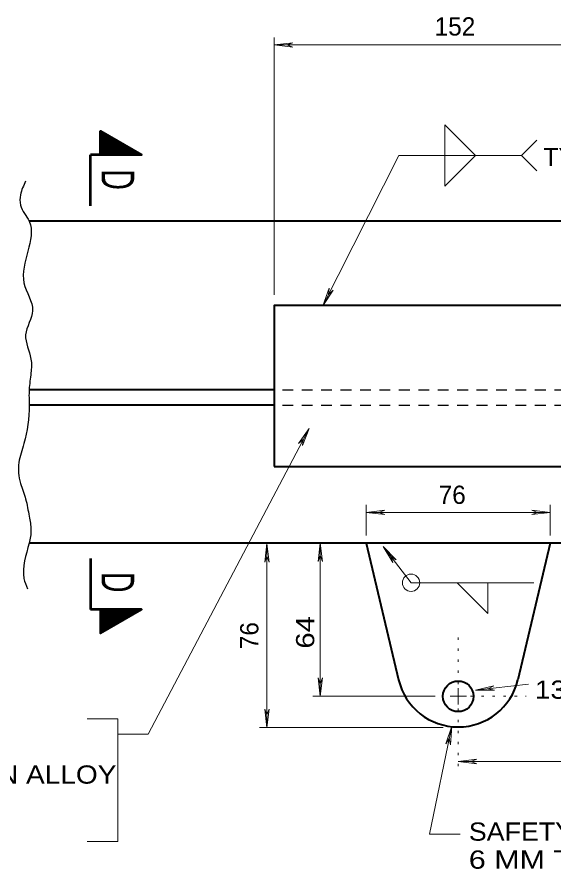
# Model space of a CAD drawing. Extents: x 312583 to 312854, y 144419 to 144597.
# Drawn here: x 312779.22 to 312801.61, y 144485.39 to 144520.9 of the extents above; entities that cross this region are included whole.
import ezdxf
from ezdxf.enums import TextEntityAlignment as Align

# ---------------------------------------------------------------- set-up
doc = ezdxf.new("R2010")
doc.units = 0
doc.header["$LTSCALE"] = 0.3
doc.linetypes.add('DOTTED', pattern=[1.5, 0.3, -1.2])
doc.linetypes.add('SHORT_DASHED', pattern=[2.7, 1.5, -1.2])
doc.layers.add('1', color=7, linetype='Continuous', lineweight=40)

msp = doc.modelspace()

# ---------------------------------------------------------------- linework, layer by layer
at = {"layer": '1', "lineweight": 13}
for p, q in [((312789.9471, 144509.318), (312789.9471, 144520.0513)), ((312789.9471, 144519.737), (312790.7214, 144519.829)), ((312789.9471, 144519.737), (312790.7214, 144519.6373)), ((312790.7214, 144519.829), (312790.4761, 144519.737)), ((312790.7214, 144519.6373), (312790.4761, 144519.737)), ((312791.9711, 144508.8656), (312795.1451, 144515.1293)), ((312800.2588, 144515.1293), (312800.8951, 144514.493)), ((312791.9711, 144508.8656), (312792.2394, 144509.594)), ((312791.9711, 144508.8656), (312792.4081, 144509.5096)), ((312792.2394, 144509.594), (312792.2088, 144509.3333)), ((312792.4081, 144509.5096), (312792.2088, 144509.3333)), ((312791.3961, 144503.752), (312784.6954, 144491.01)), ((312791.3961, 144503.752), (312790.9591, 144503.1156)), ((312791.3961, 144503.752), (312791.1278, 144503.0313)), ((312790.9591, 144503.1156), (312791.1508, 144503.292)), ((312791.1278, 144503.0313), (312791.1508, 144503.292)), ((312793.7804, 144500.5703), (312793.7804, 144499.29)), ((312801.4471, 144500.5703), (312801.4471, 144499.29)), ((312793.7804, 144500.2483), (312794.5548, 144500.3403)), ((312793.7804, 144500.2483), (312801.4471, 144500.2483)), ((312793.7804, 144500.2483), (312794.5548, 144500.1563)), ((312794.5548, 144500.3403), (312794.3094, 144500.2483)), ((312794.5548, 144500.1563), (312794.3094, 144500.2483)), ((312800.6804, 144500.3403), (312800.9258, 144500.2483)), ((312801.4471, 144500.2483), (312800.6804, 144500.3403)), ((312800.6804, 144500.1563), (312800.9258, 144500.2483)), ((312801.4471, 144500.2483), (312800.6804, 144500.1563)), ((312789.6404, 144498.9526), (312789.5484, 144498.1783)), ((312789.6404, 144491.286), (312789.6404, 144498.9526)), ((312789.6404, 144498.9526), (312789.7401, 144498.1783)), ((312791.8638, 144498.968), (312791.7718, 144498.2013)), ((312791.8638, 144492.5816), (312791.8638, 144498.968)), ((312791.8638, 144498.968), (312791.9634, 144498.2013)), ((312795.6511, 144497.312), (312794.4858, 144498.83)), ((312794.4858, 144498.83), (312795.0301, 144498.278)), ((312794.4858, 144498.83), (312794.8844, 144498.163)), ((312789.5484, 144498.1783), (312789.6404, 144498.4236)), ((312789.7401, 144498.1783), (312789.6404, 144498.4236)), ((312791.7718, 144498.2013), (312791.8638, 144498.4466)), ((312791.9634, 144498.2013), (312791.8638, 144498.4466)), ((312795.0301, 144498.278), (312794.8078, 144498.416)), ((312794.8844, 144498.163), (312794.8078, 144498.416)), ((312800.7648, 144497.312), (312795.6511, 144497.312)), ((312791.7718, 144493.3483), (312791.8638, 144493.103)), ((312791.8638, 144492.5816), (312791.7718, 144493.3483)), ((312791.9634, 144493.3483), (312791.8638, 144493.103)), ((312791.8638, 144492.5816), (312791.9634, 144493.3483)), ((312800.5465, 144493.0912), (312798.3421, 144492.8423)), ((312797.6138, 144492.5816), (312797.6138, 144492.9266)), ((312798.3421, 144492.8423), (312799.1011, 144493.0186)), ((312798.3421, 144492.8423), (312799.1241, 144492.8346)), ((312799.1011, 144493.0186), (312798.8634, 144492.896)), ((312799.1241, 144492.8346), (312798.8634, 144492.896)), ((312796.6554, 144492.5816), (312791.5494, 144492.5816)), ((312797.6138, 144492.5816), (312797.2764, 144492.5816)), ((312797.6138, 144492.5816), (312797.9588, 144492.5816)), ((312797.6138, 144492.5816), (312797.6138, 144492.2366)), ((312789.5484, 144492.0526), (312789.6404, 144491.8073)), ((312789.6404, 144491.286), (312789.5484, 144492.0526)), ((312789.7401, 144492.0526), (312789.6404, 144491.8073)), ((312789.6404, 144491.286), (312789.7401, 144492.0526)), ((312782.1424, 144491.6463), (312783.4228, 144491.6463)), ((312783.4228, 144486.5326), (312783.4228, 144491.6463)), ((312796.4178, 144486.8393), (312797.3531, 144491.332)), ((312797.3531, 144491.332), (312797.1001, 144490.596)), ((312797.3531, 144491.332), (312797.2918, 144490.5576)), ((312783.4228, 144491.01), (312784.6954, 144491.01)), ((312796.9928, 144491.286), (312789.3261, 144491.286)), ((312797.1001, 144490.596), (312797.2458, 144490.8183)), ((312797.2918, 144490.5576), (312797.2458, 144490.8183)), ((312797.6138, 144489.8676), (312798.3881, 144489.9596)), ((312798.3881, 144489.9596), (312798.1428, 144489.8676)), ((312818.0608, 144489.8676), (312797.6138, 144489.8676)), ((312797.6138, 144489.8676), (312798.3881, 144489.768)), ((312798.3881, 144489.768), (312798.1428, 144489.8676)), ((312796.4178, 144486.8393), (312797.6981, 144486.8393)), ((312782.1424, 144486.5326), (312783.4228, 144486.5326))]:
    msp.add_line(p, q, dxfattribs=at)
at = {"layer": '1', "lineweight": 35}
for p, q in [((312782.7021, 144516.1106), (312782.7174, 144516.126)), ((312782.7021, 144516.0723), (312782.7404, 144516.1183)), ((312782.7021, 144516.0263), (312782.7558, 144516.103)), ((312782.7021, 144515.9803), (312782.7711, 144516.0953)), ((312782.7021, 144515.9343), (312782.7941, 144516.0876)), ((312782.7021, 144515.9036), (312782.8094, 144516.0723)), ((312782.7021, 144515.8576), (312782.8248, 144516.0646)), ((312782.7021, 144515.8116), (312782.8478, 144516.0493)), ((312782.7021, 144515.7733), (312782.8631, 144516.0416)), ((312782.7021, 144515.735), (312782.8861, 144516.034)), ((312782.7021, 144515.6813), (312782.9014, 144516.0263)), ((312782.7021, 144515.643), (312782.9244, 144516.011)), ((312782.7021, 144515.6046), (312782.9474, 144516.0033)), ((312782.7021, 144515.551), (312782.9551, 144515.988)), ((312782.7021, 144515.5126), (312782.9781, 144515.9803)), ((312782.7021, 144515.4743), (312782.9934, 144515.9726)), ((312782.7021, 144515.4283), (312783.0088, 144515.9573)), ((312782.7021, 144515.3823), (312783.0318, 144515.9496)), ((312782.7021, 144515.344), (312783.0471, 144515.9343)), ((312782.7021, 144515.3056), (312783.0701, 144515.919)), ((312782.7021, 144515.252), (312783.0854, 144515.919)), ((312782.7021, 144515.2213), (312783.1008, 144515.9036)), ((312782.7021, 144515.1753), (312783.1314, 144515.896)), ((312782.7174, 144515.1523), (312783.1391, 144515.8806)), ((312782.7481, 144515.1523), (312783.1621, 144515.873)), ((312782.7711, 144515.1523), (312783.1851, 144515.8576)), ((312782.7941, 144515.1523), (312783.1928, 144515.8576)), ((312782.8248, 144515.1523), (312783.2158, 144515.8423)), ((312782.8401, 144515.16), (312783.2388, 144515.8346)), ((312782.8708, 144515.16), (312783.2541, 144515.8193)), ((312782.8861, 144515.1523), (312783.2694, 144515.8116)), ((312782.9168, 144515.1523), (312783.2924, 144515.7963)), ((312782.9474, 144515.1523), (312783.3078, 144515.7886)), ((312782.9628, 144515.1523), (312783.3231, 144515.781)), ((312782.9934, 144515.1523), (312783.3461, 144515.7656)), ((312783.0164, 144515.1523), (312783.3691, 144515.7503)), ((312783.0394, 144515.1523), (312783.3768, 144515.7426)), ((312783.0701, 144515.16), (312783.3998, 144515.735)), ((312783.0931, 144515.1523), (312783.4228, 144515.7273)), ((312783.1161, 144515.1523), (312783.4381, 144515.712)), ((312783.1314, 144515.1523), (312783.4534, 144515.7043)), ((312783.1621, 144515.1523), (312783.4764, 144515.689)), ((312783.1928, 144515.1523), (312783.4918, 144515.6813)), ((312783.2158, 144515.1523), (312783.5071, 144515.6736)), ((312783.2388, 144515.1523), (312783.5301, 144515.666)), ((312783.2618, 144515.1523), (312783.5454, 144515.6506)), ((312783.2848, 144515.16), (312783.5684, 144515.643)), ((312783.3154, 144515.1523), (312783.5838, 144515.6276)), ((312783.3308, 144515.1523), (312783.6068, 144515.6123)), ((312783.3614, 144515.1523), (312783.6221, 144515.6123)), ((312783.3844, 144515.1523), (312783.6374, 144515.597)), ((312783.4074, 144515.1523), (312783.6604, 144515.5893)), ((312783.4381, 144515.1523), (312783.6834, 144515.574)), ((312783.4611, 144515.1523), (312783.6911, 144515.5663)), ((312783.4841, 144515.1523), (312783.7141, 144515.551)), ((312783.5071, 144515.1523), (312783.7371, 144515.551)), ((312783.5378, 144515.1523), (312783.7448, 144515.5356)), ((312783.5608, 144515.1523), (312783.7678, 144515.528)), ((312783.5761, 144515.1523), (312783.7908, 144515.5126)), ((312783.6068, 144515.1523), (312783.8061, 144515.505)), ((312783.6298, 144515.1523), (312783.8214, 144515.4896)), ((312783.6604, 144515.1523), (312783.8444, 144515.482)), ((312783.6834, 144515.1523), (312783.8674, 144515.4743)), ((312783.7064, 144515.1523), (312783.8751, 144515.459)), ((312783.7294, 144515.1523), (312783.8981, 144515.4436)), ((312783.7524, 144515.1523), (312783.9211, 144515.436)), ((312783.7754, 144515.1523), (312783.9288, 144515.4283)), ((312783.8061, 144515.1523), (312783.9518, 144515.4206)), ((312783.8291, 144515.1523), (312783.9748, 144515.4053)), ((312783.8521, 144515.1523), (312783.9901, 144515.3976)), ((312783.8751, 144515.1523), (312784.0131, 144515.3823)), ((312783.8981, 144515.1523), (312784.0284, 144515.3746)), ((312783.9288, 144515.1523), (312784.0514, 144515.367)), ((312783.9518, 144515.1523), (312784.0668, 144515.3593)), ((312783.9748, 144515.1523), (312784.0821, 144515.344)), ((312783.9978, 144515.1523), (312784.1051, 144515.3363)), ((312784.0208, 144515.1523), (312784.1204, 144515.321)), ((312784.0514, 144515.1523), (312784.1358, 144515.3056)), ((312784.0744, 144515.1523), (312784.1588, 144515.3056)), ((312784.1051, 144515.1523), (312784.1741, 144515.2903)), ((312784.1204, 144515.1523), (312784.1894, 144515.275)), ((312784.1511, 144515.1523), (312784.2124, 144515.2673)), ((312784.1741, 144515.1523), (312784.2354, 144515.252)), ((312784.1894, 144515.1523), (312784.2508, 144515.2443)), ((312784.2201, 144515.1523), (312784.2661, 144515.2366)), ((312784.2431, 144515.1523), (312784.2891, 144515.229)), ((312784.2738, 144515.1523), (312784.3044, 144515.2136)), ((312784.2968, 144515.1523), (312784.3198, 144515.206)), ((312784.3198, 144515.1523), (312784.3428, 144515.1906)), ((312784.3428, 144515.1523), (312784.3581, 144515.183)), ((312784.3658, 144515.1523), (312784.3734, 144515.1753)), ((312784.3964, 144515.1523), (312784.3964, 144515.1676)), ((312782.7021, 144496.185), (312783.1314, 144495.4643)), ((312782.7021, 144496.139), (312783.1008, 144495.4566)), ((312782.7021, 144496.1006), (312783.0854, 144495.4413)), ((312782.7021, 144496.0546), (312783.0701, 144495.4336)), ((312782.7021, 144496.0163), (312783.0471, 144495.4183)), ((312782.7021, 144495.9703), (312783.0318, 144495.4106)), ((312782.7021, 144495.932), (312783.0088, 144495.403)), ((312782.7174, 144496.208), (312783.1391, 144495.4796)), ((312782.7481, 144496.208), (312783.1621, 144495.4796)), ((312782.7711, 144496.208), (312783.1851, 144495.495)), ((312782.7941, 144496.208), (312783.1928, 144495.5026)), ((312782.8248, 144496.208), (312783.2158, 144495.518)), ((312782.8401, 144496.2003), (312783.2388, 144495.5256)), ((312782.8708, 144496.2003), (312783.2541, 144495.541)), ((312782.8861, 144496.208), (312783.2694, 144495.541)), ((312782.9168, 144496.208), (312783.2924, 144495.5563)), ((312782.9474, 144496.208), (312783.3078, 144495.5716)), ((312782.9628, 144496.208), (312783.3231, 144495.5793)), ((312782.9934, 144496.208), (312783.3461, 144495.5946)), ((312783.0164, 144496.208), (312783.3691, 144495.6023)), ((312783.0394, 144496.208), (312783.3768, 144495.61)), ((312783.0701, 144496.2003), (312783.3998, 144495.6253)), ((312783.0931, 144496.208), (312783.4228, 144495.633)), ((312783.1161, 144496.208), (312783.4381, 144495.6483)), ((312783.1314, 144496.208), (312783.4534, 144495.656)), ((312783.1621, 144496.208), (312783.4764, 144495.6636)), ((312783.1928, 144496.208), (312783.4918, 144495.6713)), ((312783.2158, 144496.208), (312783.5071, 144495.6866)), ((312783.2388, 144496.208), (312783.5301, 144495.6943)), ((312783.2618, 144496.208), (312783.5454, 144495.7096)), ((312783.2848, 144496.2003), (312783.5684, 144495.7173)), ((312783.3154, 144496.208), (312783.5838, 144495.725)), ((312783.3308, 144496.208), (312783.6068, 144495.7403)), ((312783.3614, 144496.208), (312783.6221, 144495.748)), ((312783.3844, 144496.208), (312783.6374, 144495.7633)), ((312783.4074, 144496.208), (312783.6604, 144495.771)), ((312783.4381, 144496.208), (312783.6834, 144495.7863)), ((312783.4611, 144496.208), (312783.6911, 144495.7863)), ((312783.4841, 144496.208), (312783.7141, 144495.8016)), ((312783.5071, 144496.208), (312783.7371, 144495.8093)), ((312783.5378, 144496.208), (312783.7448, 144495.8246)), ((312783.5608, 144496.208), (312783.7678, 144495.8323)), ((312783.5761, 144496.208), (312783.7908, 144495.8476)), ((312783.6068, 144496.208), (312783.8061, 144495.8476)), ((312783.6298, 144496.208), (312783.8214, 144495.863)), ((312783.6604, 144496.208), (312783.8444, 144495.8783)), ((312783.6834, 144496.208), (312783.8674, 144495.886)), ((312783.7064, 144496.208), (312783.8751, 144495.9013)), ((312783.7294, 144496.208), (312783.8981, 144495.909)), ((312783.7524, 144496.208), (312783.9211, 144495.9166)), ((312783.7754, 144496.208), (312783.9288, 144495.932)), ((312783.8061, 144496.208), (312783.9518, 144495.9396)), ((312783.8291, 144496.208), (312783.9748, 144495.955)), ((312783.8521, 144496.208), (312783.9901, 144495.9626)), ((312783.8751, 144496.208), (312784.0131, 144495.9703)), ((312783.8981, 144496.208), (312784.0284, 144495.978)), ((312783.9288, 144496.208), (312784.0514, 144495.9933)), ((312783.9518, 144496.208), (312784.0668, 144496.001)), ((312783.9748, 144496.208), (312784.0821, 144496.0163)), ((312783.9978, 144496.208), (312784.1051, 144496.024)), ((312784.0208, 144496.208), (312784.1204, 144496.0316)), ((312784.0514, 144496.208), (312784.1358, 144496.047)), ((312784.0744, 144496.208), (312784.1588, 144496.0546)), ((312784.1051, 144496.208), (312784.1741, 144496.07)), ((312784.1204, 144496.208), (312784.1894, 144496.0853)), ((312784.1511, 144496.208), (312784.2124, 144496.093)), ((312784.1741, 144496.208), (312784.2354, 144496.1006)), ((312784.1894, 144496.208), (312784.2508, 144496.1083)), ((312784.2201, 144496.208), (312784.2661, 144496.1236)), ((312784.2431, 144496.208), (312784.2891, 144496.1313)), ((312784.2738, 144496.208), (312784.3044, 144496.1466)), ((312784.2968, 144496.208), (312784.3198, 144496.1543)), ((312784.3198, 144496.208), (312784.3428, 144496.162)), ((312784.3428, 144496.208), (312784.3581, 144496.1696)), ((312784.3658, 144496.208), (312784.3734, 144496.185)), ((312784.3964, 144496.208), (312784.3964, 144496.1926)), ((312782.7021, 144495.886), (312782.9934, 144495.3876)), ((312782.7021, 144495.8476), (312782.9781, 144495.3723)), ((312782.7021, 144495.8016), (312782.9551, 144495.3646)), ((312782.7021, 144495.7556), (312782.9474, 144495.357)), ((312782.7021, 144495.7173), (312782.9244, 144495.3493)), ((312782.7021, 144495.6713), (312782.9014, 144495.334)), ((312782.7021, 144495.6253), (312782.8861, 144495.3263)), ((312782.7021, 144495.587), (312782.8631, 144495.311)), ((312782.7021, 144495.541), (312782.8478, 144495.3033)), ((312782.7021, 144495.5026), (312782.8248, 144495.2956)), ((312782.7021, 144495.4566), (312782.8094, 144495.288)), ((312782.7021, 144495.4183), (312782.7941, 144495.2726)), ((312782.7021, 144495.3723), (312782.7711, 144495.265)), ((312782.7021, 144495.334), (312782.7558, 144495.2496)), ((312782.7021, 144495.288), (312782.7404, 144495.2343)), ((312782.7021, 144495.242), (312782.7174, 144495.2343))]:
    msp.add_line(p, q, dxfattribs=at)
at = {"layer": '1', "lineweight": 53}
for p, q in [((312782.2804, 144513.0286), (312782.2804, 144515.1523)), ((312782.7021, 144515.1523), (312782.2804, 144515.1523)), ((312782.2804, 144498.3316), (312782.2804, 144496.208)), ((312782.7021, 144496.208), (312782.2804, 144496.208))]:
    msp.add_line(p, q, dxfattribs=at)
at = {"layer": '1'}
for p, q in [((312810.3941, 144512.3846), (312779.7274, 144512.3846)), ((312789.9471, 144505.362), (312779.7274, 144505.362)), ((312789.9471, 144504.718), (312779.7274, 144504.718)), ((312810.3941, 144498.968), (312779.7274, 144498.968)), ((312793.7804, 144498.968), (312795.1298, 144493.2716)), ((312801.4471, 144498.968), (312800.1054, 144493.2716))]:
    msp.add_line(p, q, dxfattribs=at)
at = {"layer": '1', "linetype": 'SHORT_DASHED', "lineweight": 25}
for p, q in [((312790.2844, 144505.362), (312804.8894, 144505.362)), ((312790.2844, 144504.718), (312804.8894, 144504.718))]:
    msp.add_line(p, q, dxfattribs=at)
at = {"layer": '1', "linetype": 'DOTTED', "lineweight": 13}
for p, q in [((312797.6138, 144493.0953), (312797.6138, 144495.0886)), ((312798.1274, 144492.5816), (312800.4504, 144492.5816)), ((312797.6138, 144492.068), (312797.6138, 144489.5456))]:
    msp.add_line(p, q, dxfattribs=at)
at = {"layer": '1', "lineweight": 13}
for points in [[(312810.3941, 144519.737), (312805.2804, 144519.737), (312789.9471, 144519.737)], [(312798.3421, 144515.1293), (312797.0618, 144516.4096), (312797.0618, 144515.1293)], [(312795.1451, 144515.1293), (312800.2588, 144515.1293), (312800.8951, 144515.7656)], [(312798.3421, 144515.1293), (312797.0618, 144513.849), (312797.0618, 144515.1293)], [(312797.5678, 144497.312), (312798.8481, 144496.0393), (312798.8481, 144497.312)]]:
    msp.add_lwpolyline(points, dxfattribs=at)
at = {"layer": '1', "lineweight": 53}
for points in [[(312782.7021, 144515.1523), (312782.7021, 144516.1413), (312784.4118, 144515.1523)], [(312782.7021, 144496.208), (312782.7021, 144495.219), (312784.4118, 144496.208)]]:
    msp.add_lwpolyline(points, close=True, dxfattribs=at)
at = {"layer": '1'}
msp.add_lwpolyline([(312789.9471, 144502.165), (312805.2804, 144502.165), (312805.2804, 144508.8733), (312789.9471, 144508.8733)], close=True, dxfattribs=at)
at = {"layer": '1', "lineweight": 13}
msp.add_circle((312795.6511, 144497.3145), 0.3614, dxfattribs=at)
at = {"layer": '1'}
msp.add_circle((312797.6163, 144492.5816), 0.6389, dxfattribs=at)
msp.add_arc((312797.6163, 144493.8588), 2.5549, 193.28615, 346.71385, dxfattribs=at)
at = {"layer": '1', "lineweight": 25}
msp.add_spline([(312779.5818, 144514.0636), (312779.3671, 144513.4886), (312779.3671, 144513.0593), (312779.7274, 144512.3846), (312779.5128, 144509.8163), (312779.8731, 144508.6586), (312779.5818, 144507.6543), (312779.8041, 144506.6423), (312779.8041, 144506.0673), (312779.7274, 144505.362), (312779.7274, 144504.718), (312779.5128, 144503.1156), (312779.2981, 144502.326), (312779.3671, 144501.4596), (312779.5818, 144500.808), (312779.7274, 144500.0873), (312779.8041, 144499.5123), (312779.7274, 144498.968), (312779.5128, 144497.496), (312779.6584, 144497.0666)], degree=3, dxfattribs=at)

# ---------------------------------------------------------------- texts
at = {"layer": '1'}
for s, p in [('152', (312796.6333, 144520.128)), ('TYP', (312801.1724, 144514.6853)), ('76', (312796.8006, 144500.6039))]:
    msp.add_text(s, height=0.76, dxfattribs=at).set_placement(p)
at = {"layer": '1', "width": 0.65}
for p in [(312782.7481, 144514.1212), (312782.7481, 144497.3387)]:
    msp.add_text('D', height=1.365, rotation=270, dxfattribs=at).set_placement(p, align=Align.CENTER)
at = {"layer": '1'}
msp.add_text('76', height=0.76, rotation=90, dxfattribs=at).set_placement((312789.2855, 144494.5461))
at = {"layer": '1', "width": 1.2}
msp.add_text('64 ', height=0.76, rotation=90, dxfattribs=at).set_placement((312791.615, 144494.5706))
at = {"layer": '1'}
for s, width, p in [('13 MM DIA. CLEARANCE HOLE', 1.15, (312800.811, 144492.4797)), ('STIFFENER OR EXTRUSION ALLOY', 1.15, (312763.5603, 144488.9419)), ('SAFETY CHAIN ANCHORAGE LUG', 1.1, (312798.0584, 144486.5623)), ('6 MM THK. ALUM. ALLOY 6061-T6 SHEET', 1.25, (312798.0584, 144485.396))]:
    msp.add_text(s, height=0.76, dxfattribs=dict(at, width=width)).set_placement(p)

doc.saveas('drawing.dxf')
